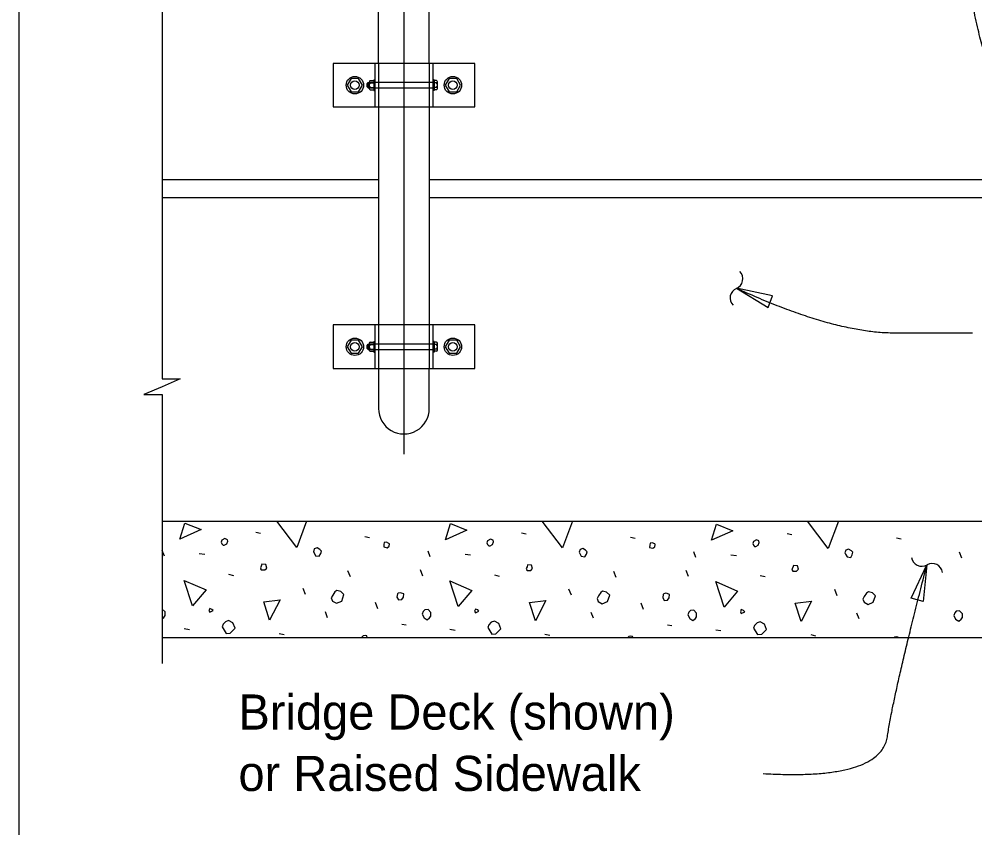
# Model space of a CAD drawing. Extents: x 0 to 41.1, y 0 to 26.4.
# Drawn here: x 0 to 5.48, y 12.71 to 17.35 of the extents above; entities that cross this region are included whole.
import ezdxf

# ---------------------------------------------------------------- set-up
doc = ezdxf.new("R2010")
doc.units = 0
for name, color, linetype in [('CL_Major', 7, 'Continuous'), ('Dimension', 7, 'Continuous'), ('Miscellaneous', 7, 'Continuous'), ('Miscellaneous1', 7, 'Continuous'), ('SteelMisc', 7, 'Continuous'), ('SteelMisc_h', 7, 'Continuous'), ('SupstrConc', 7, 'Continuous')]:
    doc.layers.add(name, color=color, linetype=linetype)

msp = doc.modelspace()

# ---------------------------------------------------------------- linework, layer by layer
at = {"layer": 'CL_Major'}
msp.add_line((2.2062, 25.6784), (2.2062, 14.8533), dxfattribs=at)
at = {"layer": 'Dimension'}
for points in [[(0.8194, 20.1983), (0.8194, 19.1806), (0.9227, 19.1806), (0.8194, 19.1356), (0.716, 19.0906), (0.8194, 19.0906), (0.8194, 16.8862)], [(0.8194, 17.1362), (0.8194, 15.2854), (0.9227, 15.2854), (0.8194, 15.2404), (0.716, 15.1954), (0.8194, 15.1954), (0.8194, 13.6529)]]:
    msp.add_lwpolyline(points, dxfattribs=at)
for points in [[(4.1133, 15.8046), (4.2942, 15.6956), (4.32, 15.7612)], [(5.2051, 14.2189), (5.1828, 14.0088), (5.1149, 14.0279)]]:
    msp.add_lwpolyline(points, close=True, dxfattribs=at)
for centre, start, end in [((4.09, 15.8588), 292.7091, 44.4364), ((4.136, 15.7489), 112.7091, 224.4364), ((5.1759, 14.2702), 188.4294, 300.1567), ((5.2358, 14.1671), 8.4294, 120.1567)]:
    msp.add_arc(centre, 0.0596, start, end, dxfattribs=at)
for points in [[(6.1, 16.8398), (5.7021, 16.8398), (5.4981, 17.1768), (5.4369, 17.6337)], [(5.467, 15.5476), (5.3703, 15.5476), (4.6709, 15.5476), (4.1132, 15.8046)], [(4.2666, 13.0222), (4.9423, 12.9828), (5.0161, 13.4901), (5.2052, 14.2189)]]:
    msp.add_open_spline(points, degree=2, dxfattribs=at)
at = {"layer": 'Miscellaneous'}
for p, q in [((1.9986, 16.9625), (1.9986, 16.9746)), ((2.0043, 16.9625), (2.0043, 16.9746)), ((1.9986, 15.4625), (1.9986, 15.4746)), ((2.0043, 15.4625), (2.0043, 15.4746)), ((1.3567, 14.4058), (1.3832, 14.4005)), ((1.9825, 14.3811), (2.009, 14.3758)), ((2.8805, 14.4023), (2.907, 14.397)), ((3.5063, 14.3775), (3.5328, 14.3722)), ((4.4043, 14.3987), (4.4308, 14.3934)), ((5.0301, 14.374), (5.0566, 14.3687)), ((0.8334, 14.2679), (0.821, 14.3015)), ((1.0332, 14.2838), (1.065, 14.2803)), ((2.3572, 14.2644), (2.3448, 14.298)), ((2.557, 14.2803), (2.5888, 14.2768)), ((3.881, 14.2609), (3.8687, 14.2944)), ((4.0808, 14.2768), (4.1126, 14.2732)), ((5.4048, 14.2573), (5.3925, 14.2909)), ((1.2011, 14.1654), (1.2294, 14.1583)), ((1.8994, 14.1495), (1.8852, 14.1848)), ((2.3148, 14.1548), (2.3006, 14.1901)), ((2.7249, 14.1619), (2.7532, 14.1548)), ((3.4232, 14.146), (3.409, 14.1813)), ((3.8386, 14.1513), (3.8245, 14.1866)), ((4.2487, 14.1583), (4.277, 14.1513)), ((1.643, 14.0487), (1.6289, 14.0841)), ((3.1669, 14.0452), (3.1527, 14.0805)), ((4.6907, 14.0417), (4.6765, 14.077)), ((2.0567, 13.9674), (2.0426, 14.0028)), ((3.5805, 13.9639), (3.5664, 13.9992)), ((1.7686, 13.9161), (1.7562, 13.9497)), ((3.2924, 13.9126), (3.28, 13.9462)), ((4.8162, 13.9091), (4.8038, 13.9427)), ((2.1946, 13.879), (2.2193, 13.8755)), ((3.7184, 13.8755), (3.7431, 13.8719)), ((0.9465, 13.8543), (0.9766, 13.849)), ((1.491, 13.826), (1.5193, 13.8189)), ((2.4704, 13.8507), (2.5004, 13.8454)), ((3.0148, 13.8224), (3.0431, 13.8154)), ((3.9942, 13.8472), (4.0242, 13.8419)), ((4.5386, 13.8189), (4.5669, 13.8118))]:
    msp.add_line(p, q, dxfattribs=at)
for points in [[(1.5918, 14.3192), (1.4776, 14.4695)], [(1.6479, 14.4695), (1.5918, 14.3192)], [(3.1156, 14.3157), (2.9987, 14.4695)], [(3.1731, 14.4695), (3.1156, 14.3157)], [(4.6394, 14.3121), (4.5198, 14.4695)], [(4.6982, 14.4695), (4.6394, 14.3121)], [(0.9218, 14.3669), (0.9501, 14.4588), (1.0438, 14.4217), (0.9218, 14.3669)], [(2.4456, 14.3634), (2.4739, 14.4553), (2.5676, 14.4182), (2.4456, 14.3634)], [(3.9694, 14.3599), (3.9977, 14.4518), (4.0914, 14.4147), (3.9694, 14.3599)], [(1.1693, 14.3316), (1.1763, 14.3316), (1.1905, 14.3386), (1.1958, 14.3545), (1.194, 14.3634), (1.1799, 14.3705), (1.1622, 14.3599), (1.1587, 14.3492), (1.1622, 14.3386), (1.1693, 14.3316)], [(2.6931, 14.328), (2.7002, 14.328), (2.7143, 14.3351), (2.7196, 14.351), (2.7178, 14.3599), (2.7037, 14.3669), (2.686, 14.3563), (2.6825, 14.3457), (2.686, 14.3351), (2.6931, 14.328)], [(4.2169, 14.3245), (4.224, 14.3245), (4.2381, 14.3316), (4.2434, 14.3475), (4.2417, 14.3563), (4.2275, 14.3634), (4.2098, 14.3528), (4.2063, 14.3422), (4.2098, 14.3316), (4.2169, 14.3245)], [(1.6908, 14.2874), (1.6996, 14.2715), (1.7208, 14.2679), (1.7297, 14.2838), (1.7332, 14.298), (1.7244, 14.3068), (1.7084, 14.3157), (1.6925, 14.3104), (1.6872, 14.2944), (1.6908, 14.2874)], [(2.0903, 14.3227), (2.1097, 14.3174), (2.1221, 14.3263), (2.1239, 14.3386), (2.1203, 14.3422), (2.1062, 14.3492), (2.0938, 14.3475), (2.0921, 14.3351), (2.0903, 14.3227)], [(3.2146, 14.2838), (3.2234, 14.2679), (3.2446, 14.2644), (3.2535, 14.2803), (3.257, 14.2944), (3.2482, 14.3033), (3.2323, 14.3121), (3.2164, 14.3068), (3.211, 14.2909), (3.2146, 14.2838)], [(3.6141, 14.3192), (3.6335, 14.3139), (3.6459, 14.3227), (3.6477, 14.3351), (3.6442, 14.3386), (3.63, 14.3457), (3.6176, 14.3439), (3.6159, 14.3316), (3.6141, 14.3192)], [(4.7384, 14.2803), (4.7472, 14.2644), (4.7685, 14.2609), (4.7773, 14.2768), (4.7808, 14.2909), (4.772, 14.2997), (4.7561, 14.3086), (4.7402, 14.3033), (4.7349, 14.2874), (4.7384, 14.2803)], [(1.3885, 14.1901), (1.4097, 14.1901), (1.4203, 14.2008), (1.415, 14.2202), (1.392, 14.222), (1.3885, 14.2114), (1.3832, 14.2025), (1.3885, 14.1901), (1.3849, 14.1937)], [(2.9123, 14.1866), (2.9335, 14.1866), (2.9441, 14.1972), (2.9388, 14.2167), (2.9158, 14.2184), (2.9123, 14.2078), (2.907, 14.199), (2.9123, 14.1866), (2.9088, 14.1901)], [(4.4361, 14.1831), (4.4573, 14.1831), (4.4679, 14.1937), (4.4626, 14.2131), (4.4396, 14.2149), (4.4361, 14.2043), (4.4308, 14.1954), (4.4361, 14.1831), (4.4326, 14.1866)], [(0.9943, 13.9833), (0.9465, 14.13), (1.0721, 14.0752), (0.9943, 13.9833)], [(2.5181, 13.9798), (2.4704, 14.1265), (2.5959, 14.0717), (2.5181, 13.9798)], [(4.0419, 13.9762), (3.9942, 14.123), (4.1197, 14.0682), (4.0419, 13.9762)], [(1.7968, 14.0116), (1.8198, 13.9992), (1.8499, 14.0116), (1.8622, 14.0487), (1.8446, 14.0664), (1.8216, 14.0717), (1.811, 14.0646), (1.7986, 14.0452), (1.7898, 14.0293), (1.7968, 14.0116)], [(2.1663, 14.0346), (2.1751, 14.0187), (2.1946, 14.0204), (2.2034, 14.0328), (2.2052, 14.0523), (2.1928, 14.0576), (2.184, 14.0593), (2.1734, 14.0558), (2.1698, 14.0523), (2.1663, 14.0346)], [(3.3207, 14.0081), (3.3436, 13.9957), (3.3737, 14.0081), (3.3861, 14.0452), (3.3684, 14.0629), (3.3454, 14.0682), (3.3348, 14.0611), (3.3224, 14.0417), (3.3136, 14.0257), (3.3207, 14.0081)], [(3.6901, 14.031), (3.699, 14.0151), (3.7184, 14.0169), (3.7272, 14.0293), (3.729, 14.0487), (3.7166, 14.054), (3.7078, 14.0558), (3.6972, 14.0523), (3.6936, 14.0487), (3.6901, 14.031)], [(4.8445, 14.0045), (4.8674, 13.9922), (4.8975, 14.0045), (4.9099, 14.0417), (4.8922, 14.0593), (4.8692, 14.0646), (4.8586, 14.0576), (4.8462, 14.0381), (4.8374, 14.0222), (4.8445, 14.0045)], [(1.4362, 13.902), (1.4026, 14.0063), (1.4963, 14.0187), (1.4362, 13.902)], [(2.96, 13.8985), (2.9264, 14.0028), (3.0201, 14.0151), (2.96, 13.8985)], [(4.4838, 13.8949), (4.4503, 13.9992), (4.5439, 14.0116), (4.4838, 13.8949)], [(0.8193, 13.91), (0.8299, 13.9179), (0.8369, 13.9285), (0.8369, 13.9497), (0.821, 13.9656), (0.8193, 13.9655)], [(1.0933, 13.948), (1.1127, 13.9568), (1.1056, 13.9639), (1.0933, 13.9692), (1.088, 13.9568), (1.0933, 13.948)], [(2.3113, 13.9356), (2.3219, 13.9144), (2.3395, 13.9038), (2.3537, 13.9144), (2.3608, 13.925), (2.3608, 13.9462), (2.3448, 13.9621), (2.3254, 13.9603), (2.3166, 13.9515), (2.3113, 13.9356)], [(2.6171, 13.9444), (2.6365, 13.9533), (2.6295, 13.9603), (2.6171, 13.9656), (2.6118, 13.9533), (2.6171, 13.9444)], [(3.8351, 13.9321), (3.8457, 13.9108), (3.8634, 13.9002), (3.8775, 13.9108), (3.8846, 13.9214), (3.8846, 13.9427), (3.8687, 13.9586), (3.8492, 13.9568), (3.8404, 13.948), (3.8351, 13.9321)], [(4.1409, 13.9409), (4.1603, 13.9497), (4.1533, 13.9568), (4.1409, 13.9621), (4.1356, 13.9497), (4.1409, 13.9409)], [(5.3589, 13.9285), (5.3695, 13.9073), (5.3872, 13.8967), (5.4013, 13.9073), (5.4084, 13.9179), (5.4084, 13.9391), (5.3925, 13.955), (5.373, 13.9533), (5.3642, 13.9444), (5.3589, 13.9285)], [(1.164, 13.8631), (1.187, 13.826), (1.2099, 13.8278), (1.2188, 13.8366), (1.2382, 13.856), (1.2258, 13.8861), (1.2011, 13.9002), (1.1834, 13.8932), (1.1693, 13.879), (1.164, 13.8631)], [(2.6878, 13.8596), (2.7108, 13.8224), (2.7338, 13.8242), (2.7426, 13.8331), (2.762, 13.8525), (2.7497, 13.8826), (2.7249, 13.8967), (2.7072, 13.8896), (2.6931, 13.8755), (2.6878, 13.8596)], [(4.2116, 13.856), (4.2346, 13.8189), (4.2576, 13.8207), (4.2664, 13.8295), (4.2859, 13.849), (4.2735, 13.879), (4.2487, 13.8932), (4.2311, 13.8861), (4.2169, 13.8719), (4.2116, 13.856)], [(1.9949, 13.8028), (1.9931, 13.8118), (1.9842, 13.8136), (1.9718, 13.8118), (1.9628, 13.8028)], [(3.518, 13.8028), (3.5169, 13.8083), (3.508, 13.8101), (3.4957, 13.8083), (3.4901, 13.8028)], [(5.0411, 13.8028), (5.0407, 13.8048), (5.0318, 13.8065), (5.0195, 13.8048), (5.0175, 13.8028)]]:
    msp.add_lwpolyline(points, dxfattribs=at)
at = {"layer": 'Miscellaneous1'}
msp.add_lwpolyline([(0, 26.4), (41.0667, 26.4), (41.0667, 0), (0, 0)], close=True, dxfattribs=at)
at = {"layer": 'SteelMisc'}
for p, q in [((2.0603, 17.0944), (2.0603, 17.7968)), ((2.352, 17.0944), (2.352, 17.7968)), ((2.6121, 17.0944), (1.8002, 17.0944)), ((1.8002, 17.0944), (1.8002, 16.8444)), ((2.0395, 17.0944), (2.0395, 16.8444)), ((2.3728, 17.0944), (2.3728, 16.8444)), ((2.6121, 16.8444), (2.6121, 17.0944)), ((2.0129, 16.9954), (2.033, 16.9954)), ((2.033, 16.9997), (2.033, 16.9391)), ((2.033, 16.9997), (2.0395, 16.9997)), ((2.033, 16.9954), (2.033, 16.9435)), ((2.3791, 16.9997), (2.3731, 16.9997)), ((2.3791, 16.9997), (2.3791, 16.9391)), ((2.3938, 16.9954), (2.3791, 16.9954)), ((2.3989, 16.95), (2.3989, 16.9889)), ((1.9958, 16.9774), (2.0014, 16.984)), ((1.9958, 16.9597), (1.9958, 16.9774)), ((1.9958, 16.9597), (2.0014, 16.9541)), ((2.0014, 16.984), (2.008, 16.984)), ((2.0014, 16.9541), (2.0014, 16.984)), ((2.0014, 16.9541), (2.008, 16.9541)), ((2.008, 16.9873), (2.008, 16.9516)), ((2.0127, 16.9824), (2.033, 16.9824)), ((2.0127, 16.9565), (2.033, 16.9565)), ((2.013, 16.9435), (2.033, 16.9435)), ((2.033, 16.9391), (2.0395, 16.9391)), ((2.3791, 16.9391), (2.3731, 16.9391)), ((2.3939, 16.9824), (2.3791, 16.9824)), ((2.3939, 16.9564), (2.3791, 16.9564)), ((2.3938, 16.9434), (2.3791, 16.9434)), ((1.8002, 16.8444), (2.6121, 16.8444)), ((2.0603, 16.8444), (2.0603, 15.5944)), ((2.352, 16.8444), (2.352, 15.5944)), ((2.6121, 15.5944), (1.8002, 15.5944)), ((1.8002, 15.5944), (1.8002, 15.3444)), ((2.0395, 15.5944), (2.0395, 15.3444)), ((2.3728, 15.5944), (2.3728, 15.3444)), ((2.6121, 15.3444), (2.6121, 15.5944)), ((1.9958, 15.4774), (2.0014, 15.484)), ((1.9958, 15.4597), (1.9958, 15.4774)), ((1.9958, 15.4597), (2.0014, 15.4541)), ((2.0014, 15.484), (2.008, 15.484)), ((2.0014, 15.4541), (2.0014, 15.484)), ((2.0014, 15.4541), (2.008, 15.4541)), ((2.008, 15.4873), (2.008, 15.4516)), ((2.0127, 15.4824), (2.033, 15.4824)), ((2.0127, 15.4565), (2.033, 15.4565)), ((2.0129, 15.4954), (2.033, 15.4954)), ((2.033, 15.4997), (2.033, 15.4391)), ((2.033, 15.4997), (2.0395, 15.4997)), ((2.033, 15.4954), (2.033, 15.4435)), ((2.3791, 15.4997), (2.3731, 15.4997)), ((2.3791, 15.4997), (2.3791, 15.4391)), ((2.3938, 15.4954), (2.3791, 15.4954)), ((2.3939, 15.4824), (2.3791, 15.4824)), ((2.3939, 15.4564), (2.3791, 15.4564)), ((2.3989, 15.45), (2.3989, 15.4889)), ((2.013, 15.4435), (2.033, 15.4435)), ((2.033, 15.4391), (2.0395, 15.4391)), ((2.3791, 15.4391), (2.3731, 15.4391)), ((2.3938, 15.4434), (2.3791, 15.4434)), ((1.8002, 15.3444), (2.6121, 15.3444)), ((2.0602, 15.3444), (2.0602, 15.1153)), ((2.3519, 15.1153), (2.3519, 15.3444))]:
    msp.add_line(p, q, dxfattribs=at)
for points in [[(1.9468, 17.007), (1.9035, 17.007), (1.8818, 16.9694), (1.9035, 16.9319), (1.9468, 16.9319), (1.9685, 16.9694)], [(2.5088, 17.007), (2.4655, 17.007), (2.4438, 16.9694), (2.4655, 16.9319), (2.5088, 16.9319), (2.5305, 16.9694)], [(1.9468, 15.507), (1.9035, 15.507), (1.8818, 15.4694), (1.9035, 15.4319), (1.9468, 15.4319), (1.9685, 15.4694)], [(2.5088, 15.507), (2.4655, 15.507), (2.4438, 15.4694), (2.4655, 15.4319), (2.5088, 15.4319), (2.5305, 15.4694)]]:
    msp.add_lwpolyline(points, close=True, dxfattribs=at)
for centre, radius in [((1.9252, 16.9694), 0.05), ((1.9252, 16.9694), 0.025), ((2.4871, 16.9694), 0.05), ((2.4871, 16.9694), 0.025), ((1.9252, 15.4694), 0.05), ((2.4871, 15.4694), 0.05), ((1.9252, 15.4694), 0.025), ((2.4871, 15.4694), 0.025)]:
    msp.add_circle(centre, radius, dxfattribs=at)
for centre, radius, start, end in [((2.0145, 16.9889), 0.00674, 104.4891, 254.1889), ((2.3921, 16.9889), 0.00673, 285.7823, 75.5404), ((2.0274, 16.9694), 0.0196, 138.628, 221.372), ((2.0145, 16.95), 0.00673, 105.7823, 255.5404), ((2.3921, 16.95), 0.00674, 284.4891, 74.1889), ((2.3792, 16.9694), 0.0196, 318.628, 41.372), ((2.0145, 15.4889), 0.00674, 104.4891, 254.1889), ((2.0274, 15.4694), 0.0196, 138.628, 221.372), ((2.0145, 15.45), 0.00673, 105.7823, 255.5404), ((2.3921, 15.4889), 0.00673, 285.7823, 75.5404), ((2.3921, 15.45), 0.00674, 284.4891, 74.1889), ((2.3792, 15.4694), 0.0196, 318.628, 41.372)]:
    msp.add_arc(centre, radius, start, end, dxfattribs=at)
msp.add_ellipse((2.2062, 15.1153), major_axis=(0, 0.1458), ratio=0.999499, start_param=1.570796, end_param=4.712389, dxfattribs=at)
at = {"layer": 'SteelMisc_h'}
for p, q in [((2.0603, 17.0944), (2.0603, 16.8444)), ((2.352, 17.0944), (2.352, 16.8444)), ((2.3729, 16.984), (2.008, 16.984)), ((2.008, 16.9541), (2.3729, 16.9541)), ((2.0603, 15.5944), (2.0603, 15.3444)), ((2.352, 15.5944), (2.352, 15.3444)), ((2.3729, 15.484), (2.008, 15.484)), ((2.008, 15.4541), (2.3729, 15.4541))]:
    msp.add_line(p, q, dxfattribs=at)
at = {"layer": 'SupstrConc'}
for p, q in [((0.8193, 16.4295), (2.0603, 16.4295)), ((2.352, 16.4295), (12.0604, 16.4295)), ((0.8193, 16.3254), (2.0603, 16.3254)), ((2.352, 16.3254), (12.0604, 16.3254)), ((0.8193, 14.4695), (23.5931, 14.4695)), ((0.8193, 13.8028), (23.5931, 13.8028))]:
    msp.add_line(p, q, dxfattribs=at)

# ---------------------------------------------------------------- texts
at = {"layer": 'Dimension'}
for s, p in [('Bridge Deck (shown)', (1.2575, 13.2743)), ('or Raised Sidewalk', (1.2575, 12.9223))]:
    msp.add_text(s, height=0.2016, dxfattribs=at).set_placement(p)

doc.saveas('drawing.dxf')
